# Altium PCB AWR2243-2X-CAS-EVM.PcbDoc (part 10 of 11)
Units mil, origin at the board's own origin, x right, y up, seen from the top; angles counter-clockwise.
Board outline 5118.11 x 3937.01 mil, 8 copper layers (Layer 1 - Top Layer, Layer 2 - GND, Layer 3 - Signal (Sensitive), Layer 4 - GND / Signal, Layer 5 - Signal, Layer 6 - PWR / Signal, Layer 7 - GND, Layer 8 - Bottom Layer), stack 54.8 mil thick; 629 components, 407 nets, 2243 pads, 3950 vias.
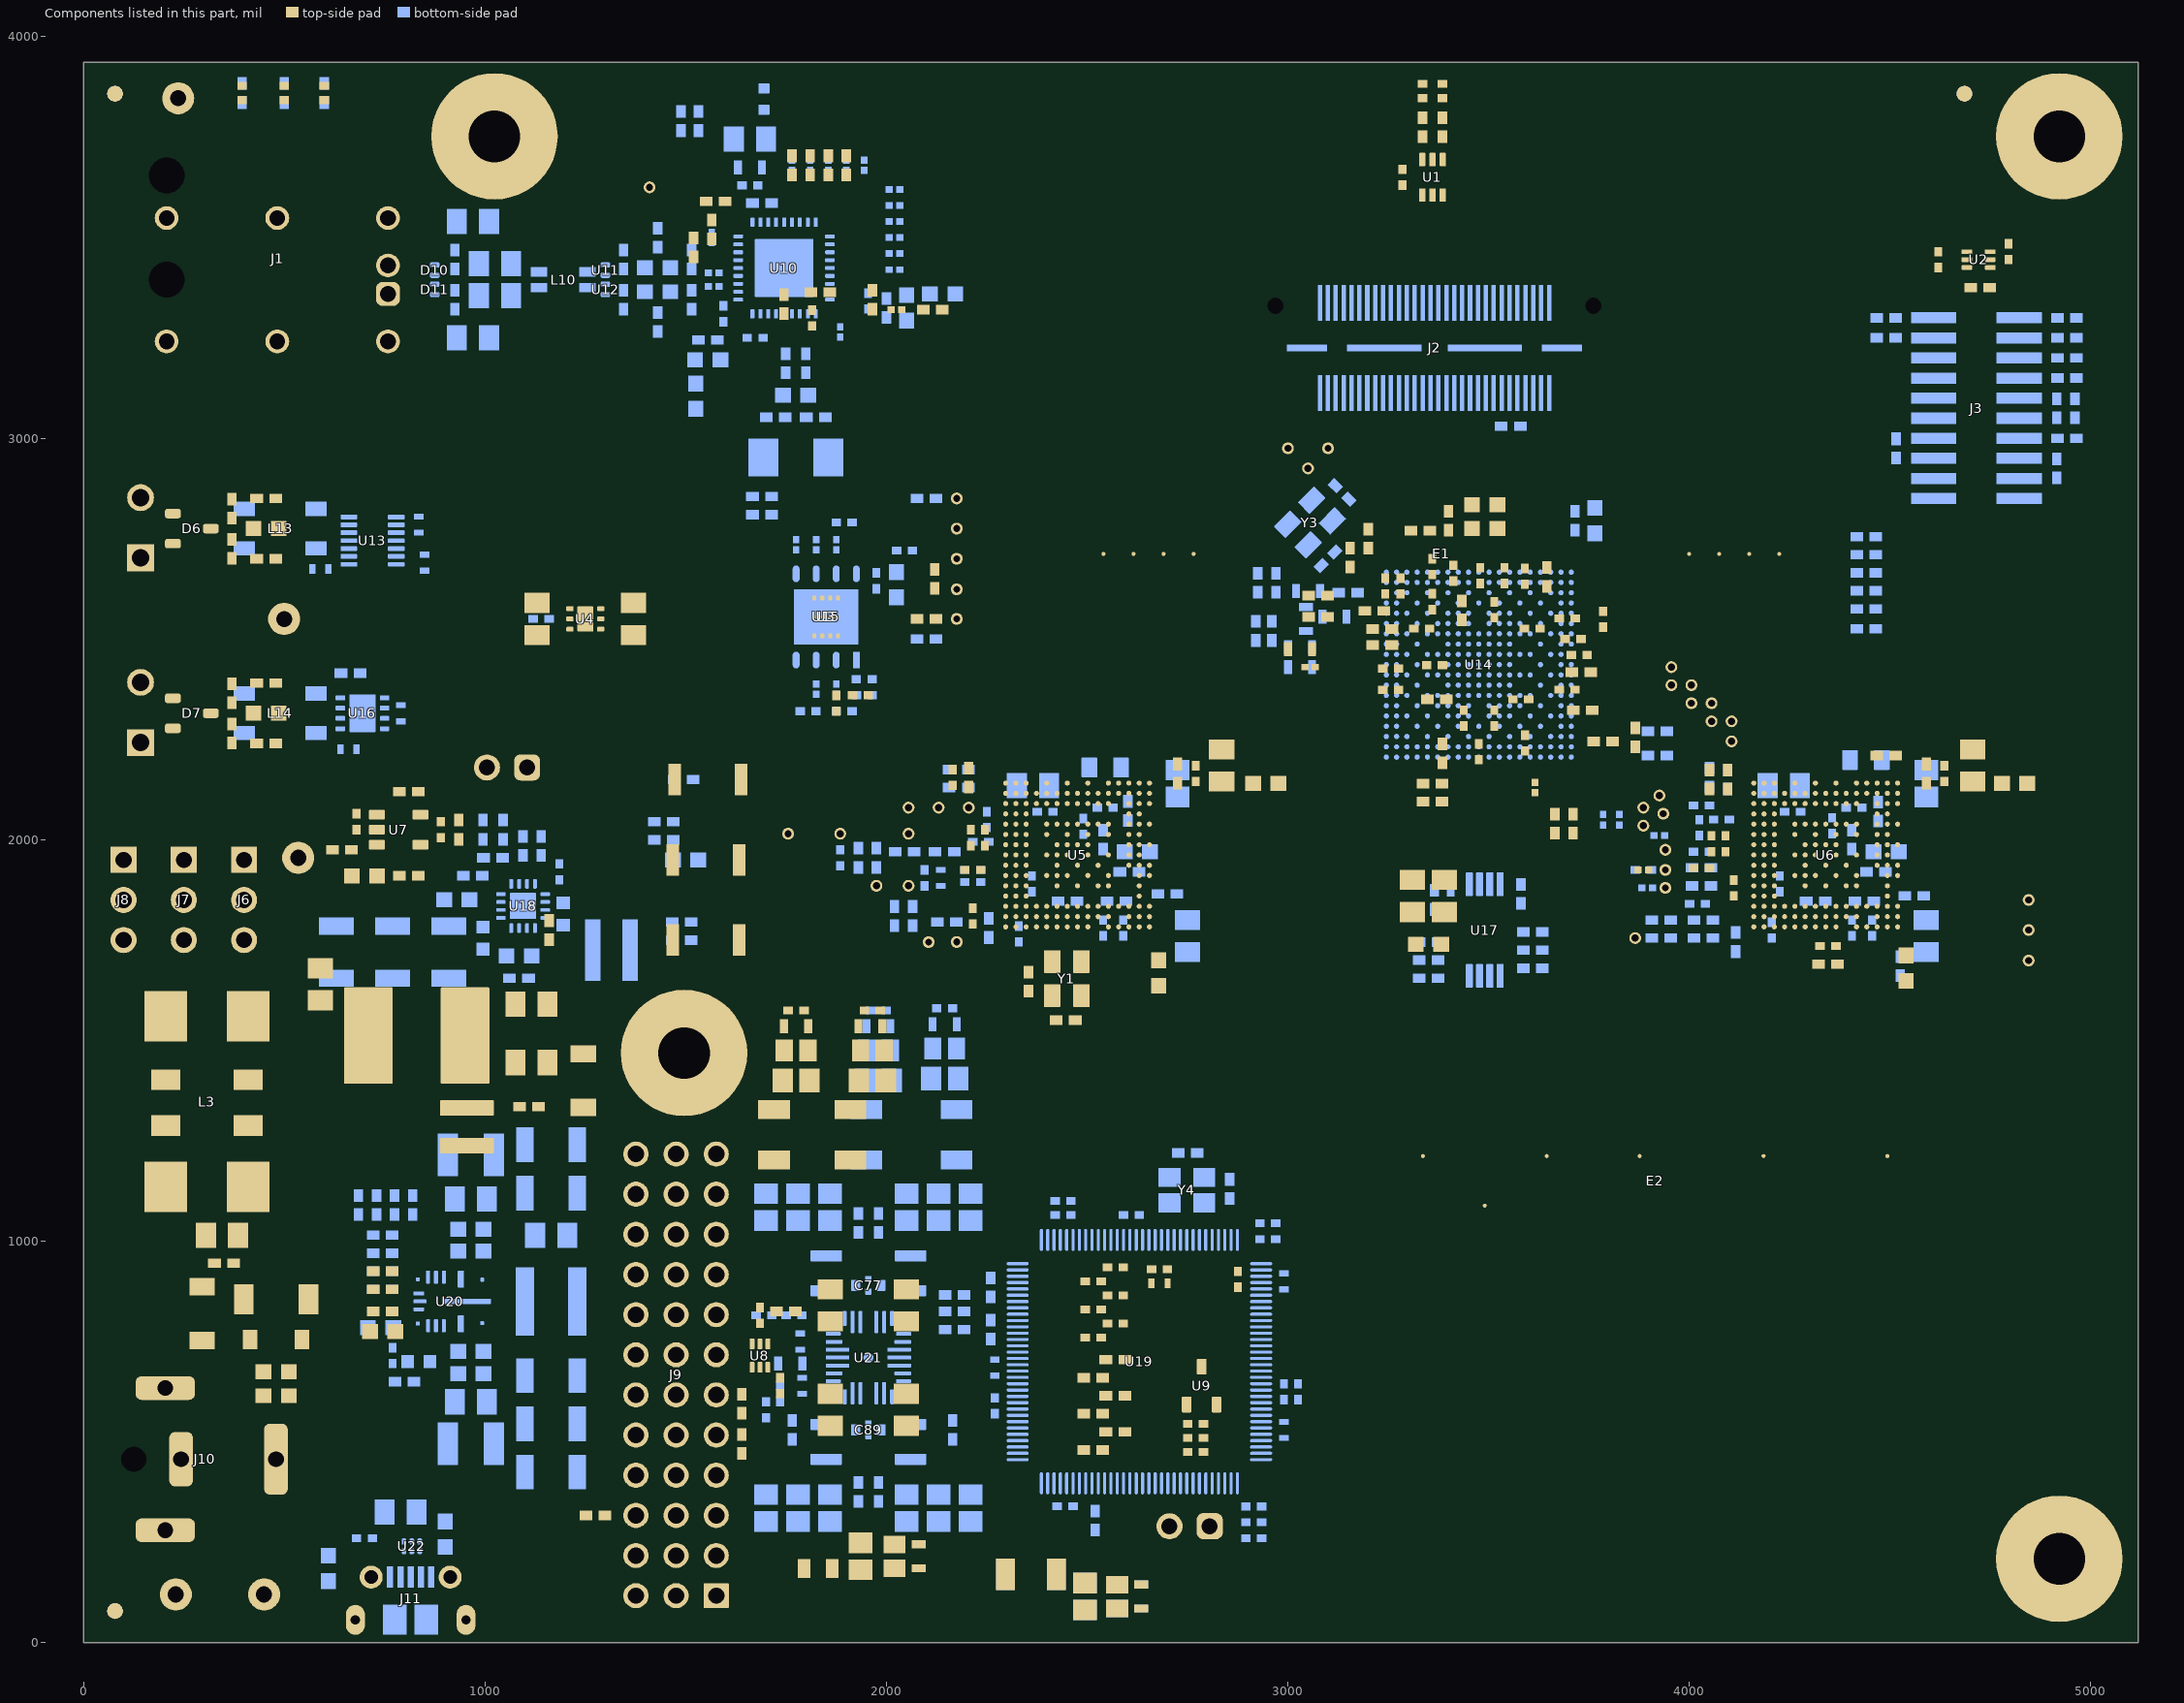
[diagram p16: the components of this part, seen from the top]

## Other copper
Layer 1 - Top Layer:
  region net GND: 700,965 690,955 550,955 535,970 535,1350 550,1365 800,1365 815,1350 815,1200 800,1185 725,1185 700,1160 700,1085 665,1050 665,1010 700,975
  region net GND: 644,2029 653,2038 758,2038 770,2050 770,2132 803,2132 803,1975 803,1898 770,1898 770,1946 770,2000 757,2013 652,2013 644,2021
  pour cut-out: 4391.12,1818.92 4415.85,1818.92 4415.87,1816 4391.12,1816
  pour cut-out: 2527.73,1818.92 2552.46,1818.92 2552.48,1816 2527.73,1816
  region net FE1_VRF1_FILTERED: 1670,1310 1670,1805 1680,1815 1785,1815 1795,1805 1795,1625 1770,1600 1770,1310 1760,1300 1680,1300
  region net GND: 540,1655 525,1670 525,1735 540,1750 660,1750 675,1735 675,1670 660,1655
  region net GND: 3230,2510 3170,2510 3150,2530 3150,2607 3127,2630 3120,2637 3120,2685 3131,2696 3217,2696 3228,2707 3272,2707 3290,2725 3411,2725 3428,2708 3528,2708 3535,2715 3610,2715 3615,2710 3615,2670 3605,2660 3445,2660 3435,2670 3400,2670 3385,2685 3340,2685 3295,2640 3290,2635 3205,2635 3195,2625 3195,2600 3210,2585 3210,2555 3230,2535
  region net GND: 3420,2266 3420,2301 3424,2305 3442,2305 3448,2311 3448,2335 3455,2342 3497,2342 3504,2335 3504,2311 3510,2305 3526,2305 3530,2301 3530,2265 3533,2262 3543,2262 3547,2266 3547,2304 3553,2310 3593,2310 3598,2315 3598,2325 3593,2330 3580,2330 3573,2337 3573,2510 3578,2515 3601,2515 3605,2519 3605,2540 3626,2561 3626,2580 3621,2585 3553,2585 3538,2570 3508,2570 3504,2566 3504,2540 3496,2532 3453,2532 3445,2540 3445,2566 3441,2570 3414,2570 3394,2590 3394,2597 3370,2621 3370,2625 3349,2625 3349,2598 3352,2595 3370,2595 3377,2588 3377,2545 3369,2537 3340,2537 3340,2515 3369,2515 3378,2506 3378,2451 3372,2445 3372,2425 3378,2419 3378,2336 3372,2330 3355,2330 3352,2327 3352,2315 3355,2312 3390,2312 3401,2301 3401,2266 3406,2261 3415,2261
  region net 1V2: 3401,2657 3401,2597 3420,2578 3447,2578 3453,2572 3453,2547 3458,2542 3493,2542 3498,2547 3498,2572 3504,2578 3522,2578 3524,2580 3524,2605 3522,2607 3505,2607 3486,2588 3469,2588 3446,2611 3430,2611 3422,2619 3422,2657
  region net 1V2: 3330,2338 3327,2341 3327,2385 3323,2389 3281,2389 3277,2393 3277,2402 3281,2406 3323,2406 3327,2410 3327,2504 3332,2509 3365,2509 3370,2504 3370,2455 3363,2448 3363,2422 3370,2415 3370,2341 3367,2338
  region net GND: 2355,1641 2434,1641 2440,1635 2440,1540 2435,1535 2390,1535 2340,1585 2340,1637 2344,1641
  region net 3V3: 1825,850 1925,850 1935,860 1935,930 1920,945 1825,945 1810,930 1810,865
  region net 3V3: 2085,850 1985,850 1975,860 1975,930 1990,945 2085,945 2100,930 2100,865
  region net 3V3: 2085,570 1985,570 1975,560 1975,490 1990,475 2085,475 2100,490 2100,555
  region net 3V3: 1825,570 1925,570 1935,560 1935,490 1920,475 1825,475 1810,490 1810,555
  region net GND: 2712,2172 2782,2172 2800,2190 2860,2190 2870,2200 2870,2250 2860,2260 2740,2260 2705,2225 2705,2179
  region net FE1_VRF2_FILTERED: 2955,2120 2945,2110 2945,2065 2950,2060 2995,2060 3000,2065 3000,2160 2990,2170 2965,2170 2955,2160
  region net NetC40_1: 2623,2118 2630,2125 2665,2125 2700,2160 2790,2160 2800,2170 2930,2170 2940,2160 2940,2125 2935,2120 2705,2120 2694,2109 2623,2109
  region net GND: 1130,1625 1145,1640 1190,1640 1280,1550 1280,1410 1270,1400 1140,1400 1130,1410
  region net GND: 2630,905 2645,920 2645,940 2650,945 2670,945 2675,940 2675,860 2670,855 2655,855 2650,860 2650,875 2630,895
  region net NetC81_1: 260,910 310,960 340,960 345,955 345,875 330,860 265,860 260,865
  region net GND: 2640,20 2655,35 2655,95 2642,108 2448,108 2435,95 2435,35 2450,20
  region net FE1_1V8_FILTERED: 2395,135 2410,120 2640,120 2655,135 2655,225 2640,240 2410,240 2395,225
  region net GND: 1890,235 1903,222 2087,222 2100,235 2100,325 2005,325 2000,320 2000,305 1990,295 1920,295 1910,305 1910,320 1905,325 1890,325
  region net 1V2_FILTERED: 1849,161 1865,145 2175,145 2190,160 2190,195 2175,210 1849,210
  region net FE1_VRF2_FILTERED: 1950,1300 1960,1310 1960,1585 1950,1595 1870,1595 1860,1585 1860,1310 1870,1300
  region net GND: 1972,1585 1982,1595 2090,1595 2100,1585 2100,1363 2092,1355 1980,1355 1972,1363
  region net GND: 1782,1585 1792,1595 1840,1595 1850,1585 1850,1365 1840,1355 1790,1355 1782,1363
  region net 1V8: 2350,355 2365,340 2365,135 2350,120 2270,120 2255,135 2255,340 2270,355
  region net GND: 1055,2540 1165,2540 1174,2531 1226,2531 1230,2535 1230,2585 1270,2585 1270,2535 1274,2531 1326,2531 1335,2540 1445,2540 1455,2530 1455,2480 1445,2470 1055,2470 1045,2480 1045,2530
  region net 3V3_LDO: 1281,2569 1326,2569 1335,2560 1445,2560 1455,2570 1455,2620 1445,2630 1294,2630 1279,2615 1279,2571
  region net VBAT: 1219,2569 1174,2569 1165,2560 1055,2560 1045,2570 1045,2620 1055,2630 1206,2630 1221,2615 1221,2571
  region net 3V3: 2120,3250 2125,3245 2175,3245 2180,3250 2180,3330 2170,3340 2130,3340 2120,3330
  region net VDDIO_ETH: 1750,3685 1915,3685 1915,3715 1910,3720 1900,3720 1885,3735 1870,3735 1860,3725 1850,3725 1840,3735 1825,3735 1815,3725 1805,3725 1795,3735 1780,3735 1765,3720 1755,3720 1750,3715
  region net GND: 290,1645 280,1655 130,1655 120,1645 120,1390 140,1370 270,1370 290,1390
  region net GND: 295,2790 330,2790 360,2820 420,2820 445,2795 445,2755 420,2730 360,2730 330,2760 295,2760
  region net VPP_LDO_OUT: 815,2050 835,2030 950,2030 965,2045 965,2090 1040,2165 1040,2200 1020,2220 835,2220 815,2200
  region net 3V3: 700,2135 755,2080 755,2055 750,2050 615,2050 605,2060 605,2125 615,2135
  region net GND: 295,2330 330,2330 360,2360 420,2360 445,2335 445,2295 420,2270 360,2270 330,2300 295,2300
  region net VBAT: 1025,1090 1000,1065 1000,640 1025,615 1025,430 1010,415 870,415 855,430 855,1270 870,1285 1010,1285 1025,1270
  region net NetC72_1: 1115,1320 1125,1310 1280,1310 1290,1320 1290,1350 1280,1360 1125,1360 1115,1350
  region net NetC63_1: 875,1325 890,1310 1090,1310 1105,1325 1105,1625 1090,1640 890,1640 875,1625
  region net NetC60_1: 350,1500 350,1390 370,1370 450,1370 465,1385 770,1385 785,1400 785,1620 770,1635 365,1635 350,1620
  region net NetC85_1: 445,540 490,585 490,770 535,815 535,895 550,910 645,910 660,895 660,365 645,350 460,350 445,365
  region net NetC75_1: 355,1195 355,1305 375,1325 495,1325 515,1305 515,835 495,815 375,815 365,825 365,920 355,930
  region net 3V3: 3345,1845 3340,1850 3255,1850 3250,1845 3250,1720 3255,1715 3340,1715 3345,1720
  region net 3V3_BUFFER: 3355,1845 3360,1850 3445,1850 3450,1845 3450,1720 3445,1715 3360,1715 3355,1720
  region net GND: 3265,1870 3255,1880 3255,1910 3280,1935 3315,1935 3345,1965 3460,1965 3470,1955 3470,1900 3440,1870
  region net FE2_VRF2_FILTERED: 4818.39,2120 4808.39,2110 4808.39,2065 4813.39,2060 4858.39,2060 4863.39,2065 4863.39,2160 4853.39,2170 4828.39,2170 4818.39,2160
  region net NetC41_1: 4486.39,2118 4493.39,2125 4528.39,2125 4563.39,2160 4653.39,2160 4663.39,2170 4793.39,2170 4803.39,2160 4803.39,2125 4798.39,2120 4568.39,2120 4557.39,2109 4486.39,2109
  region net GND: 4465,2134 4461,2138 4461,2145 4465,2149 4465,2165 4495,2195 4495,2225 4530,2260 4735,2260 4740,2255 4740,2200 4735,2195 4670,2195 4645,2170 4558,2170 4522,2134 4491,2134 4485,2140 4475,2140 4469,2134
  region net 1V2: 3500,2855 3500,2760 3480,2740 3480,2730 3485,2725 3520,2725 3545,2750 3545,2855 3540,2860 3505,2860
  region net GND: 3480,2755 3485,2760 3485,2870 3480,2875 3405,2875 3385,2855 3385,2805 3390,2800 3425,2800 3435,2790 3435,2760 3440,2755
  region net FE1_VRF1_FILTERED: 2431,2049 2448,2032 2504,2032 2521,2049 2521,2058 2431,2058
  region net FE2_VRF1_FILTERED: 4294.39,2049 4311.39,2032 4367.39,2032 4384.39,2049 4384.39,2058 4294.39,2058
  pour cut-out: 2397,2050 2397,2066 2554,2066 2554,2049 2531,2026 2523,2026 2517,2032 2512,2032 2504,2024 2448,2024 2440,2032 2435,2032 2428,2025 2422,2025
  pour cut-out: 4260.39,2050 4260.39,2066 4417.39,2066 4417.39,2049 4394.39,2026 4386.39,2026 4380.39,2032 4375.39,2032 4367.39,2024 4311.39,2024 4303.39,2032 4298.39,2032 4291.39,2025 4285.39,2025
  pour cut-out: 1790,735 1815,710 1840,710 1850,720 1850,745 1825,770 1800,770 1790,760
  pour cut-out: 1720,265 1760,265 1760,335 1720,335
  pour cut-out: 1800,265 1840,265 1840,335 1800,335
  pour cut-out: 1720,1085 1760,1085 1760,1155 1720,1155
  pour cut-out: 1800,1085 1840,1085 1840,1155 1800,1155
  text ".Layer_Name" at -2337.69,-846.49 h60
Layer 3 - Signal (Sensitive):
  pour cut-out: 2510,1480 2320,1670 2320,1830 2350,1860 2490,1860 2559,1791 2559,1768 2563,1764 2674,1764 2685,1775 2685,1835 2730,1880 2730,2120 2810,2200 3005,2200 3120,2085 3410,2085 3430,2065 3430,1975 3410,1955 3394,1955 3384,1965 3345,1965 3295,1915 3260,1915 3230,1885 3230,1820 3190,1780 3190,1715 3165,1690 2950,1690 2740,1480
  pour cut-out: 3455,1975 3475,1955 3495,1955 3505,1965 3545,1965 3555,1955 3590,1955 3615,1930 3660,1885 3660,1820 3700,1780 3700,1715 3735,1680 3735,1580 3880,1435 4275,1435 4415,1575 4415,1790 4365,1840 4260,1840 4230,1810 4230,1720 4205,1695 4085,1695 4045,1735 4045,1945 4105,2005 4105,2140 4065,2180 3625,2180 3560,2115 3525,2115 3455,2045
  pour cut-out: 3065,3259 3084,3278 3127,3278 3153,3278 3187,3278 3208,3278 3247,3278 3268,3278 3302,3278 3328,3278 3362,3278 3388,3278 3430,3278 3445,3263 3445,3235 3450,3230 3525,3230 3575,3180 3575,2990 3518,2933 3518,2888 3505,2875 3365,2875 3340,2850 3312,2850 3306,2856 3300,2856 3297,2853 3297,2841 3315,2823 3315,2800 3305,2790 3245,2790 3225,2810 3225,2900 3215,2910 3215,2980 3210,2985 3185,2985 3175,2995 3100,2995 3025,3070 3025,3200 3065,3240
  pour cut-out: 3630,2470 3660,2500 3660,2750 3780,2870 3780,3350 3750,3380 2910,3380 2850,3320 2850,3250 2820,3220 2210,3220 2180,3250 2180,3290 2160,3310 2100,3310 2020,3390 2020,3490 2000,3510 1960,3510 1940,3490 1940,3460 1910,3430 1840,3430 1820,3450 1820,3480 1800,3500 1710,3500 1680,3470 1550,3470 1540,3480 1450,3480 1435,3495 1435,3530 1455,3550 1570,3550 1580,3540 1660,3540 1690,3570 1870,3570 1900,3600 2000,3600 2080,3680 2910,3680 3010,3780 3040,3780 3120,3860 3820,3860 4190,3490 4190,2660 4020,2490 4020,2400 3980,2360 3900,2360 3870,2390 3870,2425 3785,2510 3750,2510 3740,2500 3740,2420 3690,2370 3650,2370 3630,2390
  pour cut-out: 855,175 890,210 955,210 1145,20 1645,20 1705,80 2200,80 2250,130 2250,275 2305,330 2640,330 2665,355 2850,355 2965,470 2965,1085 2925,1125 2835,1125 2795,1085 2795,1025 2805,1015 2890,1015 2905,1000 2905,495 2830,420 2640,420 2605,385 2270,385 2190,305 2190,170 2160,140 1670,140 1610,80 1185,80 990,275 830,275 790,235 790,220 780,210 780,190 795,175
  pour cut-out: 4824.43,1839.8 4824.43,1805 4810,1805 4810,1840.1
  text "LAYER 3 - SIGNAL(SENSITIVE)" at -2337.69,-847.99 h60
Layer 4 - GND / Signal:
  pour cut-out: 1810,775 cw(c1810,750) 1835,750 cw(c1810,750) 1810,725 cw(c1810,750) 1785,750 cw(c1810,750)
  pour cut-out: 1830,755 cw(c1830,730) 1855,730 cw(c1830,730) 1830,705 cw(c1830,730) 1805,730 cw(c1830,730)
  pour cut-out: 2120,695 cw(c2120,670) 2145,670 cw(c2120,670) 2120,645 cw(c2120,670) 2095,670 cw(c2120,670)
  pour cut-out: 2090,710 cw(c2090,685) 2115,685 cw(c2090,685) 2090,660 cw(c2090,685) 2065,685 cw(c2090,685)
  pour cut-out: 1935,1080 1975,1080 ccw(c1975,1105) 2000,1105 ccw(c1975,1105) 1975,1130 1935,1130 ccw(c1935,1105) 1910,1105 ccw(c1935,1105)
  pour cut-out: 1910,315 cw(c1935,315) 1935,340 1975,340 cw(c1975,315) 2000,315 2000,285 cw(c1975,285) 1975,260 1935,260 cw(c1935,285) 1910,285
  region net FE1_1V8_FILTERED: 2530,2059.01 2530,2051 2536,2045 2546,2045 2552.39,2051.39 2552.39,2057.08
  region net 1V2_FILTERED: 2508,1873.63 2495.23,1886.4 2506.6,1886.4 2511,1884 2526,1866.27 2526,1840 2512,1840 2508,1844
  region net 1V2_FILTERED: 2333.41,1884.59 2342,1876 2342,1870 2331.99,1859.99 2327,1859.99 2327,1882 2329.59,1884.59
  region net 1V2_FILTERED: 4371,1849 4375,1853 4417,1853 4417,1843 4414,1840 4375,1840 4371,1844
  pour cut-out: 4570,2085 4570,1420 4600,1420 4600,2075 4590,2085
  pour cut-out: 4245,2160 4245,2130 4530,2130 4530,2160
  pour cut-out: 4002.36,2184.71 4159.71,2184.71 4165,2190 4175,2190 4180.29,2184.71 4190.52,2184.71 4190.52,2195 4002.36,2195
  pour cut-out: 2340,2095 2340,2045 2520,2045 2520,2095
  text "LAYER 4-GND/SIGNAL" at -2337.69,-847.99 h60
Layer 5 - Signal:
  region net FE1_1V8_FILTERED: 2585,1815 2590,1810 2610,1810 2635,1835 2650,1835 2655,1840 2655,1875 2650,1880 2600,1880 2570,1850 2570,1845 2585,1830
  pour cut-out: 5079.89,660.9 5110,660.9 5110,680 5079.89,680
  pour cut-out: 4975.27,3300 4975.27,3240 4990,3240 4990,3300
  pour cut-out: 2285,3140 2285,3175 2310,3175 2310,3134.89 2284.33,3134.89
  text "LAYER 5 - SIGNAL" at -2337.69,-847.99 h60
Layer 7 - GND:
  text "LAYER 7 - GND" at -2337.69,-847.99 h60
Layer 2 - GND:
  pour cut-out: 2373.62,2123.35 cw(c2373.62,2115.55) 2381.42,2115.55 cw(c2373.62,2115.55) 2373.62,2107.75 cw(c2373.62,2115.55) 2365.82,2115.55 cw(c2373.62,2115.55)
  pour cut-out: 2424.8,2123.35 cw(c2424.8,2115.55) 2432.6,2115.55 cw(c2424.8,2115.55) 2424.8,2107.75 cw(c2424.8,2115.55) 2417,2115.55 cw(c2424.8,2115.55)
  pour cut-out: 2475.98,2123.35 cw(c2475.98,2115.55) 2483.78,2115.55 cw(c2475.98,2115.55) 2475.98,2107.75 cw(c2475.98,2115.55) 2468.18,2115.55 cw(c2475.98,2115.55)
  pour cut-out: 2527.17,2123.35 cw(c2527.17,2115.55) 2534.96,2115.55 cw(c2527.17,2115.55) 2527.17,2107.75 cw(c2527.17,2115.55) 2519.37,2115.55 cw(c2527.17,2115.55)
  pour cut-out: 2629.53,2072.17 cw(c2629.53,2064.37) 2637.33,2064.37 cw(c2629.53,2064.37) 2629.53,2056.57 cw(c2629.53,2064.37) 2621.73,2064.37 cw(c2629.53,2064.37)
  pour cut-out: 2629.53,2020.99 cw(c2629.53,2013.19) 2637.33,2013.19 cw(c2629.53,2013.19) 2629.53,2005.39 cw(c2629.53,2013.19) 2621.73,2013.19 cw(c2629.53,2013.19)
  pour cut-out: 2629.53,1969.81 cw(c2629.53,1962.01) 2637.33,1962.01 cw(c2629.53,1962.01) 2629.53,1954.21 cw(c2629.53,1962.01) 2621.73,1962.01 cw(c2629.53,1962.01)
  pour cut-out: 4390.55,2123.35 cw(c4390.55,2115.55) 4398.35,2115.55 cw(c4390.55,2115.55) 4390.55,2107.75 cw(c4390.55,2115.55) 4382.75,2115.55 cw(c4390.55,2115.55)
  pour cut-out: 4339.37,2123.35 cw(c4339.37,2115.55) 4347.17,2115.55 cw(c4339.37,2115.55) 4339.37,2107.75 cw(c4339.37,2115.55) 4331.57,2115.55 cw(c4339.37,2115.55)
  pour cut-out: 4288.19,2123.35 cw(c4288.19,2115.55) 4295.99,2115.55 cw(c4288.19,2115.55) 4288.19,2107.75 cw(c4288.19,2115.55) 4280.39,2115.55 cw(c4288.19,2115.55)
  pour cut-out: 4237.01,2123.35 cw(c4237.01,2115.55) 4244.81,2115.55 cw(c4237.01,2115.55) 4237.01,2107.75 cw(c4237.01,2115.55) 4229.21,2115.55 cw(c4237.01,2115.55)
  pour cut-out: 4492.91,1969.81 cw(c4492.91,1962.01) 4500.71,1962.01 cw(c4492.91,1962.01) 4492.91,1954.21 cw(c4492.91,1962.01) 4485.12,1962.01 cw(c4492.91,1962.01)
  pour cut-out: 4492.91,2020.99 cw(c4492.91,2013.19) 4500.71,2013.19 cw(c4492.91,2013.19) 4492.91,2005.39 cw(c4492.91,2013.19) 4485.12,2013.19 cw(c4492.91,2013.19)
  pour cut-out: 4492.91,2072.17 cw(c4492.91,2064.37) 4500.71,2064.37 cw(c4492.91,2064.37) 4492.91,2056.57 cw(c4492.91,2064.37) 4485.12,2064.37 cw(c4492.91,2064.37)
  region net GND: 2640,3100 2640,3070 2665,3070 2665,3100
  text "LAYER 2 - GND" at -2337.69,-847.99 h60
Layer 6 - PWR / Signal:
  pour cut-out: 670,925 cw(c690,925) 690,945 cw(c690,925) 710,925 cw(c690,925) 690,905 cw(c690,925)
  pour cut-out: 1720,470 2235,470 2285,520 2285,855 2260,880 2260,1135 2330,1205 2330,1220 2250,1140 2250,871.81 2275,846.81 2275,530 2225,480 1715,480 1690,455 1690,365 1715,340 2400,340 2500,440 2500,990 2475,1015 2475,1130 2755,1410 2895,1410 3075,1590 3075,1995 3064.29,1984.29 3064.29,1594.29 2890,1420 2750,1420 2465,1135 2465,1005 2490,980 2490,445 2395,350 1720,350 1700,370 1700,450
  pour cut-out: 2670,170 2690,190 2990,190 3100,300 3100,1120 3150,1170 4205,1170 4260,1225 4260,2075 4240,2095 4240,2845 4315,2920 4450,2920 4500,2870 4500,2795 4455,2750 4455,2455 4550,2360 4995,2360 5085,2270 5085,2295 5005,2375 4560,2375 4470,2465 4470,2740 4515,2785 4515,2880 4460,2935 4305,2935 4225,2855 4225,2080 4245,2060 4245,1235 4195,1185 3140,1185 3085,1130 3085,310 2980,205 2660,205 2660,170
  region net VDDIO_ETH: 1510,3535 1510,3595 1570,3655 1620,3655 1710,3745 1885,3745 1895,3735 1895,3665 1885,3655 1755,3655 1710,3610 1625,3610 1550,3535
  pour cut-out: 1765,3606.65 1855,3606.65 1855,3645 1765,3645
  pour cut-out: 1065,386.65 1003.06,386.65 990,399.71 1051.94,399.71
  pour cut-out: 1065,1278.35 1018.35,1278.35 1015,1275 1015,1260 1055,1260 1065,1270
  text "LAYER 6 - PWR/SIGNAL" at -2337.69,-847.99 h60
Layer 8 - Bottom Layer:
  region net GND: 1965,485 1965,565 ccw(c1952.93,565) 1961.46,573.54 1960,575 1960,660 1950,660 1950,575 1948.54,573.54 ccw(c1957.07,565) 1945,565 1945,485
  region net GND: 1945,935 1945,855 ccw(c1957.07,855) 1948.54,846.46 1950,845 1950,760 1960,760 1960,845 1961.46,846.46 ccw(c1952.93,855) 1965,855 1965,935
  region net 3V3: 1980,649 1980,586.49 ccw(c2000.48,586.49) 1986,572 cw(c1954.61,540.62) 1999,540.62 1999,505 cw(c1989,505) 1989,495 1984,495 cw(c1984,505) 1974,505 1974,564.34 ccw(c1960.34,564.34) 1970,574 cw(c1972.41,576.41) 1969,576.41 1969,649
  region net 3V3: 1930,649 1930,586.49 cw(c1909.51,586.49) 1924,572 ccw(c1955.38,540.62) 1911,540.62 1911,505 ccw(c1921,505) 1921,495 1926,495 ccw(c1926,505) 1936,505 1936,564.34 cw(c1949.66,564.34) 1940,574 ccw(c1937.59,576.41) 1941,576.41 1941,649
  region net 3V3: 1980,771 1980,833.51 cw(c2000.48,833.51) 1986,848 ccw(c1954.61,879.38) 1999,879.38 1999,915 ccw(c1989,915) 1989,925 1984,925 ccw(c1984,915) 1974,915 1974,855.66 cw(c1960.34,855.66) 1970,846 ccw(c1972.41,843.59) 1969,843.59 1969,771
  region net 3V3: 1930,771 1930,833.51 ccw(c1909.51,833.51) 1924,848 cw(c1955.38,879.38) 1911,879.38 1911,915 cw(c1921,915) 1921,925 1926,925 cw(c1926,915) 1936,915 1936,855.66 ccw(c1949.66,855.66) 1940,846 cw(c1937.59,843.59) 1941,843.59 1941,771
  region net SW_B2: 1910,649 1910,587 1895.95,572.95 cw(c1884,584.9) 1884,568 1821,568 1810,557 1810,529 1898,529 1902,533 1902,538.79 cw(c1953.21,538.79) 1917,575 ccw(c1907.34,584.66) 1921,584.66 1921,649
  region net SW_B1: 2000,649 2000,587 2014.05,572.95 ccw(c2026,584.9) 2026,568 2089,568 2100,557 2100,529 2012,529 2008,533 2008,538.79 ccw(c1956.79,538.79) 1993,575 cw(c2002.66,584.66) 1989,584.66 1989,649
  region net SW_B3: 1910,771 1910,833 1895.95,847.05 ccw(c1884,835.1) 1884,852 1821,852 1810,863 1810,891 1898,891 1902,887 1902,881.21 ccw(c1953.21,881.21) 1917,845 cw(c1907.34,835.34) 1921,835.34 1921,771
  region net SW_B4: 2000,771 2000,833 2014.05,847.05 cw(c2026,835.1) 2026,852 2089,852 2100,863 2100,891 2012,891 2008,887 2008,881.21 cw(c1956.79,881.21) 1993,845 ccw(c2002.66,835.34) 1989,835.34 1989,771
  region net GND: 3451,1700 3461,1690 3461,1631 3439,1631 3420,1650 3420,1695 3425,1700
  region net GND: 1970,3335 1988,3317 2073,3317 2080,3310 2080,3260 2070,3250 2002,3250 1988,3264 1988,3290 1978,3300 1935,3300 1920,3315 1920,3325 1930,3335
  region net 3V3: 1665,3850 1715,3850 1720,3855 1720,3895 1715,3900 1610,3900 1605,3895 1605,3855 1610,3850
  region net GND: 855,845 785,845 775,835 775,820 770,815 750,815 730,795 730,880 750,860 805,860 810,855 855,855
  region net GND: 735,985 690,985 650,1025 650,1150 685,1185 810,1185 825,1200 825,1275 860,1310 950,1310 970,1290 970,1270 1155,1270 1225,1340 1225,1585 1205,1605 1025,1605 985,1645 535,1645 495,1605 495,795 530,760 735,760 740,765 740,890 735,895 680,895 665,910 665,930 690,955 735,955 740,960 740,980
  region net FE2_VRF1_FILTERED: 2300,1525 2445,1380 4810,1380 4950,1520 4950,2100 4775,2275 4460,2275 4450,2285 4450,2305 4460,2315 4495,2350 4880,2350 5085,2145 5085,1465 4920,1300 4870,1250 2366.18,1248.82 2315,1300 2230,1300 2225,1300 2225,1550 2250,1525
  region net 3V3: 1335,1800 1345,1810 1425,1810 1435,1800 1435,1655 1425,1645 1345,1645 1335,1655
  region net XDS_3V3: 2781,425 2784,422 2784,364 2793,355 2820,355 2840,335 2840,265 2830,255 2775,255 2765,265 2765,310 2740,335 2648,335 2634,349 2634,424 2635,425 2642,425 2643,424 2643,362 2650,355 2750,355 2759,364 2759,422 2762,425
  region net GND: 3445,3225 3445,3250 3450,3255 3520,3255 3525,3250 3525,3225
  region net GND: 2971,2464 2984,2477 2984,2493 2989,2498 3011,2498 3011,2412 2984,2412 2971,2425
  region net GND: 3030,2640 3040,2630 3040,2615 3080,2575 3095,2575 3100,2570 3100,2542 3096,2538 3075,2538 3063,2550 3010,2550 3000,2560 3000,2630 3010,2640
  region net 3V3_FLASH: 1900,2655 1915,2640 1945,2640 1955,2650 1995,2650 2005,2640 2040,2640 2050,2650 2050,2685 2040,2695 2040,2730 1965,2805 1905,2805 1900,2800
  region net 3V3: 2050,2730 2065,2745 2125,2745 2130,2740 2130,2700 2125,2695 2065,2695 2050,2710
  region net GND: 2286,1777 2291,1772 2291,1761 2299,1753 2316,1753 2321,1758 2340,1758 2340,1733 2337,1730 2233,1730 2205,1758 2205,1770 2212,1777
  region net 1V2_FILTERED: 2240,1790 2245,1785 2295,1785 2300,1780 2300,1769 2305,1764 2313,1764 2320,1771 2338,1771 2340,1773 2340,1800 2335,1805 2295,1805 2279,1821 2244,1821 2240,1817
  region net GND: 2250,2161 2256,2167 2350,2167 2354,2163 2354,2104 2350,2100 2303,2100 2300,2103 2300,2130 2286,2144 2256,2144 2250,2150
  region net GND: 2626,1777 2636,1787 2636,1824 2640,1828 2645,1828 2649,1824 2649,1787 2659,1777 2670,1777 2674,1773 2674,1749 2670,1745 2583,1745 2580,1748 2580,1774 2583,1777
  region net FE1_VRF1_FILTERED: 2512,2040 2521,2049 2521,2054 2540,2073 2540,2200 2450,2290 2245,2290 2235,2280 2235,2255 2245,2245 2385,2245 2455,2175 2455,2078 2431,2054 2431,2047 2438,2040
  region net GND: 2787,2147 2800,2160 2800,2200 2775,2225 2585,2225 2560,2200 2560,2160 2573,2147
  region net FE1_VRF2_FILTERED: 2588,2097 2580,2105 2580,2130 2585,2135 2765,2135 2780,2120 2990,2120 3000,2110 3000,2055 2990,2045 2730,2045 2700,2075 2593,2075 2588,2080
  region net FE1_1V8_FILTERED: 2413,2045 2409,2045 2402,2052 2402,2081 2378,2105 2378,2157 2355,2180 2284.98,2180 2270,2194.97 2270,2205 2295,2230 2380,2230 2435,2175 2435,2068 2425,2058 2425,2052 2419,2046 2418,2045
  region net FE1_1V8_FILTERED: 2580,1866 2594,1880 2690,1880 2695,1875 2695,1850 2705,1840 2770,1840 2785,1825 2785,1775 2780,1770 2720,1770 2715,1775 2715,1795 2675,1835 2635,1835 2625,1825 2625,1795 2615,1785 2583,1785 2580,1788 2580,1828
  region net 3V3: 1180,1270 1195,1285 1295,1285 1310,1270 1310,395 1295,380 1195,380 1180,395
  region net GND: 535,1730 550,1745 1014,1745 1062,1793 1062,1868 1128,1868 1128,1802 1096,1802 1090,1796 1090,1740 1080,1730 1080,1695 1075,1690 1000,1690 985,1675 985,1645 970,1630 550,1630 535,1645
  region net 5V: 1052,1811 1052,1802 1010,1760 580,1760 560,1780 560,1855 585,1880 795,1880 864,1811
  region net XDS_3V3: 2299,735 2395,735 2400,740 2400,754 2395,759 2299,759
  region net GND: 780,295 775,290 705,290 700,295 700,365 710,375 770,375 780,365
  region net XDSET_1_VBUS: 831,274 815,290 805,290 800,295 800,365 810,375 920,375 930,365 930,290 920,280 885,280 865,260 865,248 861,244 834,244 831,247
  region net GND: 2755,1205 2763,1197 2763,1134 2869,1134 2880,1145 2880,1175 2820,1235 2760,1235 2755,1230
  region net FE2_1V8_FILTERED: 2395,135 2410,120 2745,120 2755,130 2755,165 2745,175 2565,175 2520,220 2410,220 2395,205
  region net GND: 2640,20 2655,35 2655,95 2642,108 2458,108 2445,95 2445,35 2460,20
  region net GND: 1987,1586 1996,1595 2133,1595 2138,1590 2138,1376 2122,1360 1998,1360 1987,1371
  region net FE2_VRF1_FILTERED: 2130,1310 2130,1350 2150,1370 2150,1590 2155,1595 2180,1595 2240,1535 2240,1310 2230,1300 2140,1300
  region net FE2_VRF2_FILTERED: 1985,1300 1995,1310 1995,1347 1975,1367 1975,1590 2000,1615 2000,1655 1995,1660 1925,1660 1920,1655 1920,1600 1930,1590 1930,1505 1900,1475 1900,1310 1910,1300
  region net GND: 2008,1150 2000,1142 2000,1100 2008,1092 2240,1092 2250,1102 2250,1142 2242,1150
  region net GND: 1902,1150 1910,1142 1910,1100 1902,1092 1671,1092 1667,1096 1667,1147 1670,1150
  region net GND: 2008,328 2000,320 2000,280 2010,270 2240,270 2250,280 2250,320 2242,328
  region net GND: 1902,328 1910,320 1910,280 1900,270 1670,270 1660,280 1660,320 1668,328
  region net 1V0_A: 1540,905 1560,885 1750,885 1805,940 1915,940 1945,970 1945,1035 1940,1040 1915,1040 1895,1060 1895,1075 1890,1080 1650,1080 1620,1050 1560,1050 1540,1030
  region net 1V2: 1540,440 1575,475 1910,475 1945,440 1945,385 1940,380 1905,380 1895,370 1895,345 1890,340 1650,340 1595,285 1560,285 1540,305
  region net GND: 1950,659 1925,684 1925,736 1950,761 1960,761 1985,736 1985,684 1960,659
  region net 3V3: 1138,1870 1150,1882 1150,1898 1165,1913 1198,1913 1210,1925 1250,1925 1255,1920 1255,1880 1250,1875 1183,1875 1167,1859 1138,1859
  region net NetC167_1: 1161,1830 1181,1810 1285,1810 1295,1800 1295,1655 1285,1645 1250,1645 1150,1745 1150,1789 1138,1801 1138,1830
  region net 5V: 738,2308 740,2310 850,2310 855,2305 855,2265 850,2260 803,2260 768,2295 740,2295 738,2297
  region net 3V3: 2150,3380 2150,3340 2120,3310 2120,3250 2125,3245 2175,3245 2195,3265 2195,3380 2190,3385 2155,3385
  region net VDDIO_ETH: 1847,3380 1848,3379 1901,3379 1931,3349 1971,3349 1990,3330 2120,3330 2130,3340 2130,3380 2120,3390 1848,3390 1847,3389
  region net GND: 980,3285 1050,3285 1060,3275 1060,3220 1050,3210 980,3210
  region net GND: 980,3575 1050,3575 1060,3565 1060,3510 1050,3500 980,3500
  region net GND: 1560,3270 1580,3290 1580,3300 1585,3305 1605,3305 1610,3300 1610,3280 1627,3263 1663,3263 1666,3260 1666,3239 1615,3188 1615,3085 1610,3080 1565,3080 1560,3085
  region net 3V3_LDO: 1640,3080 1635,3085 1635,3190 1680,3235 1680,3261 1700,3281 1700,3321 1701,3322 1710,3322 1711,3321 1711,3268 1705,3262 1705,3205 1695,3195 1695,3085 1690,3080
  region net NetC98_1: 1721,3526 1720,3527 1720,3552 1697,3575 1697,3599 1686,3610 1676,3610 1666,3620 1665.06,3779.94 1650,3795 1475,3795 1470,3800 1470,3830 1475,3835 1676,3835 1721,3835 1731,3825 1731,3527 1730,3526
  region net NetL13_2: 685,2771.06 577,2771.06 550,2744.06 550,2709.06 555,2704.06 605,2704.06 610,2709.05 610,2739.05 629,2758.06 685,2758.06
  region net NetL13_1: 685,2778 577,2778 550,2805 550,2840 555,2845 605,2845 610,2840 610,2810 629,2791 685,2791
  region net NetL14_2: 652,2309 564,2309 545,2290 545,2250 550,2245 605,2245 610,2250 610,2280 625,2295 652,2295
  region net NetL14_1: 652,2321 564,2321 545,2340 545,2380 550,2385 605,2385 610,2380 610,2350 625,2335 652,2335
  region net VBAT: 955,820 955,430 940,415 870,415 855,430 855,655 855,659 869,673 884,673 889,678 889,689 893,693 893,723 925,755 925,820
  region net VBAT: 955,880 955,1270 940,1285 870,1285 855,1270 855,1045 890,1010 890,975 925,940 925,880
  region net SW: 895,840 1020,840 1055,805 1055,775 1070,760 1125,760 1125,940 1070,940 1055,925 1055,895 1020,860 895,860
  region net GND: 970,820 1015,820 1040,795 1040,760 1065,735 1150,735 1155,730 1155,395 1140,380 985,380 970,395
  region net GND: 970,880 1015,880 1040,905 1040,940 1065,965 1150,965 1155,970 1155,1270 1140,1285 985,1285 970,1270
  region net 3V3_BUFFER: 3350,1840 3355,1845 3459,1845 3468,1854 3468,1918 3470,1920 3485,1920 3487,1918 3487,1817 3445,1775 3355,1775 3350,1780
  region net GND: 3345,1855 3340,1860 3340,1960 3345,1965 3430,1965 3435,1960 3435,1950 3425,1940 3425,1860 3420,1855
  region net FE2_1V8_FILTERED: 4443.39,1866 4457.39,1880 4548.39,1880 4558.39,1870 4558.39,1840 4568.39,1830 4618.39,1830 4623.39,1825 4623.39,1775 4618.39,1770 4558.39,1770 4553.39,1775 4553.39,1800 4518.39,1835 4498.39,1835 4470,1806.61 4470,1790 4465,1785 4446.39,1785 4443.39,1788 4443.39,1828
  region net FE2_VRF2_FILTERED: 4455,2093.39 4443.39,2105 4443.39,2130 4448.39,2135 4628.39,2135 4643.39,2120 4853.39,2120 4863.39,2110 4863.39,2055 4853.39,2045 4593.39,2045 4563.39,2075 4460,2075 4455,2080
  region net 1V2_FILTERED: 4101,1763 4101,1783 4125,1807 4215,1807 4217,1805 4217,1780 4215,1778 4193,1778 4178,1763 4170,1763 4165,1768 4165,1779 4159,1785 4138,1785 4132,1779 4132,1754 4128,1750 4105,1750 4101,1754
  region net GND: 4632,2147 4670,2185 4670,2250 4660,2260 4485,2260 4455,2230 4455,2170 4478,2147
  region net FE2_VRF1_FILTERED: 4377,2042 4384,2049 4384,2059 4390.22,2066 4398,2066 4403,2071 4403,2113 4435,2145 4435,2235 4475,2275 4495,2275 4500,2280 4500,2345 4495,2350 4430,2350 4320,2240 4320,2080 4294,2054 4294,2049 4301,2042
  region net FE2_1V8_FILTERED: 4280,2045 4283,2048 4283,2054 4305,2076 4305,2255 4420,2370 4490,2370 4500,2380 4500,2410 4490,2420 4370,2420 4240,2290 4240,2113 4264,2089 4264,2052 4271,2045
  region net GND: 4173,2100 4140,2133 4140,2205 4155,2220 4210,2220 4225,2205 4225,2105 4220,2100
  region net GND: 1685,3575 1685,3596 1682,3599 1664,3599 1653,3610 1653,3772 1640,3785 1580,3785 1565,3770 1565,3620 1615,3570 1680,3570
  region net GND: 2552,2091 2552,2063 2558,2057 2558,2048 2561,2045 2570,2045 2573,2048 2573,2065 2578,2070 2578,2091 2574,2095 2556,2095
  region net GND: 2559,2022 2562,2019 2612,2019 2615,2022 2615,2063 2612,2066 2589,2066 2586,2063 2586,2045 2579,2038 2562,2038 2559,2035
  region net GND: 2518,2032 2521,2029 2521,1997 2518,1994 2460,1994 2457,1997 2457,2005 2484,2032
  region net GND: 2559,1953 2563,1957 2563,1984 2569,1990 2612,1990 2615,1987 2615,1946 2612,1943 2562,1943 2559,1946
  region net GND: 2559,1930 2563,1934 2596,1934 2600,1930 2600,1896 2596,1892 2563,1892 2559,1896
  region net GND: 2533,1876 2537,1880 2568,1880 2572,1876 2572,1819 2568,1815 2563,1815 2552,1826 2541,1826 2533,1834
  region net GND: 2456,1837 2458,1835 2491,1835 2493,1837 2493,1869 2482,1880 2461,1880 2456,1875
  region net GND: 2352,1897 2354,1895 2365,1895 2368,1892 2391,1892 2393,1894 2393,1918 2386,1925 2355,1925 2352,1922
  region net GND: 2528,1774 2531,1777 2570,1777 2573,1774 2573,1748 2570,1745 2531,1745 2528,1748
  region net GND: 2527,1981 2508,1962 2508,1946 2511,1943 2537,1943 2553,1959 2553,1993 2550,1996 2530,1996 2527,1993
  region net GND: 2386,2082 2393,2075 2393,2022 2389,2018 2366,2018 2362,2022 2362,2079 2365,2082
  region net GND: 2378,1945 2383,1940 2399,1940 2404,1935 2404,1870 2408,1866 2432,1866 2456,1890 2541,1890 2547,1896 2547,1928 2541,1934 2506,1934 2497,1943 2497,1976 2490,1983 2457,1983 2448,1992 2448,2026 2442,2032 2421,2032 2378,1989
  region net GND: 4249.39,2082 4256.39,2075 4256.39,2022 4252.39,2018 4227,2018 4224,2021 4224,2079 4227,2082
  region net GND: 4415.39,2091 4415.39,2063 4421.39,2057 4421.39,2048 4424.39,2045 4433.39,2045 4436.39,2048 4436.39,2065 4441.39,2070 4441.39,2091 4437.39,2095 4419.39,2095
  region net GND: 4422.39,2022 4425.39,2019 4480,2019 4483,2022 4483,2063 4480,2066 4452.39,2066 4449.39,2063 4449.39,2045 4442.39,2038 4425.39,2038 4422.39,2035
  region net GND: 4422.39,1953 4426.39,1957 4426.39,1984 4432.39,1990 4477,1990 4480,1987 4480,1946 4477,1943 4425.39,1943 4422.39,1946
  region net GND: 4422.39,1930 4426.39,1934 4459.39,1934 4463.39,1930 4463.39,1896 4459.39,1892 4426.39,1892 4422.39,1896
  region net GND: 4396.39,1876 4400.39,1880 4431.39,1880 4435.39,1876 4435.39,1819 4431.39,1815 4426.39,1815 4415.39,1826 4404.39,1826 4396.39,1834
  region net GND: 4394,1773 4397,1776 4416,1776 4442,1776 4471,1776 4495,1800 4495,1820 4503,1828 4509,1828 4512,1825 4512,1793 4508,1789 4504,1789 4490,1775 4490,1765 4510,1745 4510,1735 4505,1730 4411,1730 4394,1747
  region net GND: 4318,1837 4321,1834 4354,1834 4357,1837 4357,1878 4354,1881 4321,1881 4318,1878
  region net GND: 4390.39,1981 4371.39,1962 4371.39,1946 4374.39,1943 4400.39,1943 4416.39,1959 4416.39,1993 4413.39,1996 4393.39,1996 4390.39,1993
  region net GND: 4381.39,2032 4384.39,2029 4384.39,1997 4381.39,1994 4323.39,1994 4320.39,1997 4320.39,2005 4347.39,2032
  region net GND: 4215.39,1897 4217.39,1895 4228.39,1895 4231.39,1892 4254.39,1892 4256.39,1894 4256.39,1918 4249.39,1925 4218.39,1925 4215.39,1922
  region net GND: 4242.19,1944.19 4246.39,1940 4262.39,1940 4267.39,1935 4267.39,1870 4271.39,1866 4295.39,1866 4319.39,1890 4404.39,1890 4410.39,1896 4410.39,1928 4404.39,1934 4369.39,1934 4360.39,1943 4360.39,1976 4353.39,1983 4320.39,1983 4311.39,1992 4311.39,2026 4305.39,2032 4284.39,2032 4274,2032 4269,2027 4269,1998 4275.19,1991.81 4275.19,1974 4262.39,1961 4246.39,1961 4242.19,1956.81
  text ".Layer_Name" at -2340,-845 h60

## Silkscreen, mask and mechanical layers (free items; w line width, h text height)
Top Overlay:
  lines w6: 2680,1140 2690,1140 ; 2685,1105 2685,1150 ; 3145,2195 3145,2205 ; 3180,2200 3135,2200 ; 2685,1150 2695,1140 2675,1140 2685,1150 ; 3135,2200 3145,2190 3145,2210 3135,2200 ; 4445,2365 4455,2355 4455,2375 4445,2365
  lines w7: 3500,2935 3500,2920 3745,2920 3745,2935 ; 3565,2710 3622.5,2767.5 3622.5,2920 ; 4450,2365 4525,2365 4595,2435 ; 4510,2600 4490,2600 4490,2540 4630,2400 4630,2345 4660,2345
  text "GND" at 190,3710 h50
  text "'.PRJ_Title'" at 622.82,2989.87 h150
  text "'.PRJ_Number' '.PCB_Rev'" at 1050,2850 h125
  text "VBAT" at 575,2510 h50
  text "TPR RESET" at 1195,2135 h50
  text "CAN WAKE" at 1195,1935 h50
  text "GND" at 485,1810 h50
  text "Enet WAKE" at 1195,1735 h50
  text "GND" at 185,20 h50
  text "3.3V" at 410,20 h50
  text ".Layer_Name" at -2337.69,-846.49 h60
Bottom Overlay:
  lines w6: 1433.5,3209.5 1504,3280 1545,3280 1565,3300 ; 1510,3515 1545,3515 ; 1590,3440 1590,3530 ; 1650,865 1650,840 1655,835 ; 1690,665 1705,665 1715,655 ; 1760,2075 1760,2060 1900,2060 1995,2060 ; 1765,2375 1795,2375 ; 1995,2075 1995,2060 ; 2095,2005 2095,2030 2080,2045 2010,2045 1995,2060 ; 2805,2760 2805,2740 2870,2740 2930,2740 ; 2930,2760 2930,2740 ; 3025,2660 3025,2685 2970,2740 2930,2740 ; 3965,2130 3990,2105
  text "TI 20-pin" at 4810,3390 h50
  text "2" at 4620,3345 h50
  text "1" at 4835,3345 h50
  text "CAN2" at 195,2950 h50
  text "CAN1" at 195,2490 h50
  text "LDO OUT" at 935,2160 h50
  text "GND" at 150,1635 h50
  text "OFF" at 290,1635 h50
  text "RUN" at 445,1635 h50
  text "RX" at 130,1585 h50
  text "(LDO)" at 305,1585 h50
  text "(SOP2)" at 470,1585 h50
  text "TX" at 130,1535 h50
  text "ON" at 280,1535 h50
  text "FLASH" at 470,1535 h50
  text "XDS110 POWER" at 3065,180 h50
  text ".Layer_Name" at -2337.69,-846.49 h60
  text ".Layer_Name" at -2337.69,-846.49 h60
Top Paste:
  text ".Layer_Name" at -2337.69,-846.49 h60
Bottom Paste:
  text ".Layer_Name" at -2337.69,-846.49 h60
Top Solder:
  region: 3065,1220 3065,1160 2670,1160 2610,1100 2260,1100 2260,1525 2490,1525 2515,1550 2515,1720 2570,1775 2570,1792 2588,1792 2588,1779 2592,1775 2592,1765 2619,1765 2619,1792.02 2638,1792.02 2638,1782 2646,1774 2646,1766 2656,1756 2656,1729 2650,1723 2650,1606 2706,1606 2706,1922 2670,1922 2670,1953 2621,1953 2621,1971 2670,1971 2670,2004 2621,2004 2621,2022 2670,2022 2670,2056 2621,2056 2621,2073 2670,2073 2670,2102 2878,2102 2940,2040 3010,2040 3035,2065 3035,2160 3005,2190 2880,2190 2880,2265 2785,2265 2785,2230 2715,2230 2695,2210 2695,2190 2685,2180 2603,2180 2587,2164 2587,2137 2582,2132 2569,2132 2569,2160 2536,2160 2536,2107 2518,2107 2518,2160 2485,2160 2485,2107 2467,2107 2467,2160 2434,2160 2434,2107 2416,2107 2416,2160 2382,2160 2382,2107 2365,2107 2365,2160 2335,2160 2335,2570 2815,2570 2815,2470 2930,2355 2995,2355 3125,2225 3125,1695 3155,1665 4390,1665 4410,1685 4410,1768 4433,1768 4433,1792 4450,1792 4450,1768 4480,1768 4480,1570 4575,1570 4575,1922 4535,1922 4535,1953 4484,1953 4484,1971 4535,1971 4535,2004 4484,2004 4484,2022 4535,2022 4535,2056 4484,2056 4484,2073 4535,2073 4535,2102 4704,2102 4806,2000 4806,1220
  region: 3950,2565 3950,2485 4198,2237 4198,2160 4228,2160 4228,2107 4246,2107 4246,2160 4279,2160 4279,2107 4297,2107 4297,2160 4331,2160 4331,2107 4348,2107 4348,2160 4382,2160 4382,2107 4399,2107 4399,2160 4432.28,2160 4432.28,2565
  text ".Layer_Name" at -2337.69,-846.49 h60
  text ".Layer_Name" at -2337.69,-846.49 h60
Bottom Solder:
  text ".Layer_Name" at -2337.69,-846.49 h60
Drill Guide:
  text ".Layer_Name" at -2337.69,-846.49 h60
M1 Board Outline:
  the board outline again, w7.01
  text ".Layer_Name" at -2337.69,-846.49 h60
M2 Board Dimensions:
  text ".Layer_Name" at -2337.69,-846.49 h60
M3 3D STEP Top:
  text ".Layer_Name" at -2337.69,-846.49 h60
M4 3D STEP Bottom:
  text ".Layer_Name" at -2337.69,-846.49 h60
M5 Assembly Top:
  lines w10: -2811.69,-918.16 3788.31,-918.16 ; -2811.69,-714.83 3790.31,-714.83 ; -2811.69,-511.49 -2811.69,-1121.49 1193.31,-1121.49 3790.31,-1121.49 3790.31,-511.49 -2811.19,-511.49 -2811.19,-1121.49 -1235.69,-1121.49 ; -346.69,-1121.49 -346.69,-511.49 ; 920.31,-714.83 920.31,-511.49 ; 1760.31,-714.83 1760.31,-511.49 ; 2382.31,-1127.99 2382.31,-925.16
  text "Board = 100mm x 130mm" at 1635,4510 h60
  text "COMPONENTS MARKED 'DNP' SHOULD NOT BE POPULATED." at -1366.19,-306.49 h60
  text "ASSEMBLY VARIANT:" at -1366.69,-421.99 h60
  text ".VariantName" at -330.69,-421.99 h60
  text "PCB VIEWED FROM TOP SIDE" at -2748.19,-643.66 h60
  text "BOARD #:" at -271.69,-643.66 h60
  text ".PRJ_Number" at 273.81,-643.66 h60
  text "REV:" at 1118.31,-643.66 h60
  text ".PCB_Rev" at 1409.81,-643.66 h60
  text "SVN REV:" at 1956.31,-643.66 h60
  text ".VersionControl_RevNumber" at 2462.31,-643.66 h60
  text "TID #:" at -271.69,-846.99 h60
  text ".TID" at 273.81,-846.99 h60
  text "PLOT NAME =" at -2748.19,-1052.33 h60
  text ".plot_File_Name" at -1942.69,-1052.33 h60
  text "GENERATED    :" at -269.69,-1052.33 h60
  text ".Print_Date" at 599.81,-1052.33 h60
  text ".Print_Time" at 1328.81,-1052.33 h60
  text "TEXAS INSTRUMENTS" at 2593.31,-1052.33 h60
M6 Assembly Bottom:
  lines w10: -2812.19,-715.33 3789.81,-715.33 ; -2810.19,-918.66 3789.81,-918.66 ; -1404.19,-1128.49 -1404.19,-925.66 ; -782.19,-715.33 -782.19,-511.99 ; 57.81,-715.33 57.81,-511.99 ; 1324.81,-1121.99 1324.81,-511.99 ; 2213.81,-1121.99 3789.31,-1121.99 3789.31,-511.99 -2812.19,-511.99 -2812.19,-1121.99 -215.19,-1121.99 3789.81,-1121.99 3789.81,-511.99
  text "COMPONENTS MARKED 'DNP' SHOULD NOT BE POPULATED." at 3582.31,-305.99 h60
  text ".VariantName" at 2538.31,-421.99 h60
  text "ASSEMBLY VARIANT:" at 3577.31,-421.99 h60
  text ".VersionControl_RevNumber" at -1484.19,-644.16 h60
  text "SVN REV:" at -978.19,-644.16 h60
  text ".PCB_Rev" at -431.69,-644.16 h60
  text "REV:" at -140.19,-644.16 h60
  text ".PRJ_Number" at 704.31,-644.16 h60
  text "BOARD #:" at 1249.81,-644.16 h60
  text "PCB VIEWED FROM BOTTOM SIDE" at 3726.31,-644.16 h60
  text ".TID" at 704.31,-847.49 h60
  text "TID #:" at 1249.81,-847.49 h60
  text "TEXAS INSTRUMENTS" at -1615.19,-1052.83 h60
  text ".Print_Time" at -350.69,-1052.83 h60
  text ".Print_Date" at 378.31,-1052.83 h60
  text "GENERATED    :" at 1247.81,-1052.83 h60
  text ".plot_File_Name" at 2920.81,-1052.83 h60
  text "PLOT NAME =" at 3726.31,-1052.83 h60
M9 Title Sheet:
  drawing of 1178 lines, arcs and shapes, not listed
  text "1" at -2179.85,8048.51 h70
  text "2" at 315.81,8048.51 h70
  text "3" at 2805.16,8048.51 h70
  text "4" at 5311.83,8048.51 h70
  text "5" at 7810.81,8048.51 h70
  text "6" at 10315.81,8048.51 h70
  text "A" at -3336.19,6905.51 h70
  text "A" at 11463.81,6905.51 h70
  text "B" at -3336.19,4525.51 h70
  text "B" at 11463.81,4525.51 h70
  text "C" at -3336.19,2150.51 h70
  text "C" at 11463.81,2150.51 h70
  text "PROJECT TITLE:" at 8423.81,289.51 h45
  text ".PRJ_Title" at 8473.81,156.18 h70
  text "DESIGNED FOR:" at 8423.81,-11.49 h45
  text ".PRJ_Customer" at 8473.81,-151.49 h70
  text "D" at -3336.19,-219.49 h70
  text "D" at 11463.81,-219.49 h70
  text "FILE NAME:" at 8423.81,-311.49 h45
  text ".PCB_File_Name_No_Path" at 8473.81,-431.49 h70
  text "Texas Instruments (TI) and/or its licensors do not warrant the accuracy or completeness of this specification" at 3454.31,-593.33 h45
  text "ENGINEER:" at 8423.81,-601.49 h45
  text "LAYOUT BY:" at 9928.81,-601.49 h45
  text "or any information contained therein. TI and/or its licensors do not warrant that this design will meet" at 3409.33,-706 h45
  text ".PRJ_Engineer" at 8473.81,-756.48 h70
  text "JMM" at 9932,-790 h100
  text "s  o  l  u  t  i  o  n  s" at 10790,-793 h68
  text "the specifications, will be suitable for your application or fit for any particular purpose, or will operate in" at 3409.33,-818.66 h45
  text ".Layer_Name" at -2342.69,-846.49 h60
  text "ALTIUM DESIGNER VERSION:" at 9928.81,-911.49 h45
  text "an implementation. TI and/or its licensors do not warrant that the design is production worthy. You should" at 3409.33,-931.33 h45
  text "completely validate and test your design implementation to confirm the system functionality for your application." at 3454.31,-1043.99 h45
  text ".print_Scale" at 8473.81,-1044.82 h70
  text ".Application_BuildNumber" at 9979.31,-1044.82 h70
  text "1" at -2179.85,-1251.49 h70
  text "2" at 315.81,-1251.49 h70
  text "3" at 2805.16,-1251.49 h70
  text "4" at 5311.83,-1251.49 h70
  text "5" at 7810.81,-1251.49 h70
  text "6" at 10315.81,-1251.49 h70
